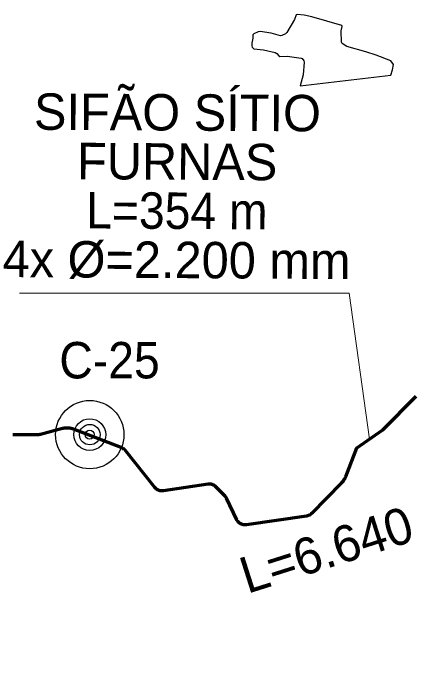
# Model space of a CAD drawing. Extents: x -1643653 to 4543381, y 1624270 to 13878484.
# Drawn here: x 717468 to 721845, y 8953455 to 8960656 of the extents above; entities that cross this region are included whole.
import ezdxf
from ezdxf.enums import TextEntityAlignment as Align

# ---------------------------------------------------------------- set-up
doc = ezdxf.new("R2010")
doc.units = 0
doc.header["$LTSCALE"] = 160
doc.linetypes.add('LONG_DASHED', pattern=[7.5, 6, -1.5])
for name, color, linetype, lineweight in [('15', 7, 'Continuous', 25), ('21', 7, 'Continuous', 25), ('50', 7, 'Continuous', 13), ('60', 7, 'Continuous', 13), ('61', 7, 'Continuous', 70)]:
    doc.layers.add(name, color=color, linetype=linetype, lineweight=lineweight)

msp = doc.modelspace()

# ---------------------------------------------------------------- linework, layer by layer
at = {"layer": '15'}
for radius in [375, 175, 112.5, 50]:
    msp.add_circle((718309, 8956027.8), radius, dxfattribs=at)
at = {"layer": '21'}
for points in [[(721081.2, 8960508.1), (721077.4, 8960519.1), (720747.7, 8960615.2), (720662.9, 8960634.1), (720587.2, 8960643), (720575.8, 8960636.9), (720556, 8960586.9), (720470.6, 8960443.6), (720458.9, 8960430), (720418.1, 8960410.7), (720402.2, 8960408.3), (720301.9, 8960437.2), (720181, 8960453.2), (720156.1, 8960451.2), (720109.1, 8960428.1), (720098.9, 8960418.5), (720097.9, 8960382.4), (720087.7, 8960324.8), (720086.7, 8960296.8), (720091.3, 8960280.8), (720111.5, 8960263.6), (720216.2, 8960251.9), (720344.2, 8960222.5), (720362.4, 8960214), (720382.8, 8960188), (720394.4, 8960180.7), (720474.7, 8960182.3), (720628.9, 8960163.3), (720641.9, 8960157.8), (720658.4, 8960133.9), (720662.8, 8960119.5), (720650.8, 8959977.9), (720618.4, 8959856.9), (721612.4, 8959974.7)], [(721612.4, 8959974.7), (721632.5, 8960032.7), (721644.1, 8960093.2), (721614, 8960131.4), (721452.9, 8960193.9), (721340.2, 8960231.7), (721132.5, 8960290.7), (721078, 8960323.4), (721072, 8960337.7), (721069.2, 8960462.3), (721081.2, 8960508.1)]]:
    msp.add_lwpolyline(points, dxfattribs=at)
at = {"layer": '50'}
msp.add_lwpolyline([(721381.2, 8955978.9), (721156.9, 8957582.7), (717536.9, 8957582.7)], dxfattribs=at)
at = {"layer": '60', "lineweight": 25}
msp.add_spline([(814781, 9009175.5), (814787.2, 9009173.4), (814796.9, 9009173.4), (814799.4, 9009172.4), (814805.1, 9009174.5), (814805.6, 9009176.5), (814811.7, 9009179.5), (814811.7, 9009179.5), (814801.5, 9009181), (814790.7, 9009181.5), (814784.1, 9009183.1), (814777.4, 9009185.1), (814778.4, 9009175.5)], degree=3, dxfattribs=at)
at = {"layer": '61', "linetype": 'LONG_DASHED'}
msp.add_line((721235.5, 8955878.6), (721527, 8956079.3), dxfattribs=at)
at = {"layer": '61'}
for points in [[(721527, 8956079.3), (721893.7, 8956451.7)], [(718108.6, 8956094.1), (718104.7, 8956095.1), (718100.8, 8956095.9), (718096.9, 8956096.7), (718092.9, 8956097.4), (718089, 8956098), (718085, 8956098.6), (718081, 8956099), (718077.1, 8956099.4), (718073.1, 8956099.7), (718069.1, 8956100), (718065.1, 8956100.1), (718061.1, 8956100.2), (718057.1, 8956100.2), (718053.1, 8956100.1), (718049.1, 8956099.9), (718045.1, 8956099.6), (718041.1, 8956099.3), (718037.1, 8956098.9), (718033.2, 8956098.4), (718029.2, 8956097.8), (718025.3, 8956097.2), (718021.3, 8956096.4), (718017.4, 8956095.6), (718013.5, 8956094.7), (718009.6, 8956093.8), (718008.8, 8956093.6), (717769.5, 8956030.4), (717765.7, 8956029.4), (717761.8, 8956028.5), (717757.8, 8956027.7), (717753.9, 8956027), (717750, 8956026.3), (717746, 8956025.7), (717742.1, 8956025.2), (717738.1, 8956024.8), (717734.1, 8956024.4), (717730.1, 8956024.1), (717726.1, 8956023.9), (717722.1, 8956023.8), (717718.1, 8956023.8), (717717.5, 8956023.8), (717484.9, 8956024.9), (717480.9, 8956025), (717476.9, 8956025.1), (717473, 8956025.3), (717469, 8956025.6), (717465, 8956026)], [(719791.3, 8955356.8), (719692.9, 8955455.4), (719690.8, 8955457.3), (719688.8, 8955459.2), (719686.6, 8955461.1), (719684.4, 8955462.9), (719682.2, 8955464.6), (719679.9, 8955466.3), (719677.6, 8955467.9), (719675.2, 8955469.4), (719672.8, 8955470.9), (719670.3, 8955472.3), (719667.8, 8955473.6), (719665.3, 8955474.9), (719662.7, 8955476.1), (719660.1, 8955477.2), (719657.5, 8955478.2), (719654.8, 8955479.2), (719652.2, 8955480.1), (719649.5, 8955480.9), (719646.7, 8955481.6), (719644, 8955482.3), (719641.2, 8955482.8), (719638.4, 8955483.3), (719635.6, 8955483.8), (719632.8, 8955484.1), (719630, 8955484.4), (719627.2, 8955484.5), (719624.3, 8955484.7), (719621.5, 8955484.7), (719618.7, 8955484.6), (719615.9, 8955484.5), (719613, 8955484.3), (719610.2, 8955484), (719607.4, 8955483.6), (719607.3, 8955483.6), (719117.6, 8955410.2), (719114.8, 8955409.8), (719112, 8955409.6), (719109.2, 8955409.3), (719106.4, 8955409.2), (719103.5, 8955409.1), (719100.7, 8955409.2), (719097.9, 8955409.2), (719095.1, 8955409.4), (719092.2, 8955409.7), (719089.4, 8955410), (719086.6, 8955410.5), (719083.8, 8955410.9), (719081.1, 8955411.5), (719078.3, 8955412.2), (719075.6, 8955412.9), (719072.9, 8955413.7), (719070.2, 8955414.6), (719067.5, 8955415.6), (719064.9, 8955416.6), (719062.3, 8955417.7), (719059.7, 8955418.9), (719057.2, 8955420.1), (719054.7, 8955421.5), (719052.2, 8955422.9), (719049.8, 8955424.3), (719047.5, 8955425.8), (719045.1, 8955427.5), (719042.8, 8955429.1), (719040.6, 8955430.8), (719038.4, 8955432.6), (719036.3, 8955434.5), (719034.2, 8955436.4), (719032.2, 8955438.4), (719030.2, 8955440.4), (719028.3, 8955442.5), (719026.4, 8955444.6), (719024.8, 8955446.5), (718696.3, 8955855.6), (718694.5, 8955857.8), (718692.7, 8955860), (718690.8, 8955862), (718688.8, 8955864), (718686.7, 8955866), (718684.7, 8955867.9), (718682.5, 8955869.8), (718680.3, 8955871.5), (718678.1, 8955873.3), (718675.8, 8955874.9), (718673.4, 8955876.5), (718671.1, 8955878), (718668.6, 8955879.5), (718666.2, 8955880.9), (718663.7, 8955882.2), (718661.1, 8955883.4), (718658.6, 8955884.6), (718655.9, 8955885.7), (718654.2, 8955886.4), (718131.5, 8956086.9), (718127.7, 8956088.3), (718123.9, 8956089.6), (718120.1, 8956090.9), (718116.3, 8956092), (718112.5, 8956093.1), (718108.6, 8956094.1)], [(721235.5, 8955878.6), (721115.9, 8955565.7), (721114.4, 8955562), (721112.9, 8955558.3), (721111.2, 8955554.7), (721109.6, 8955551)], [(721109.6, 8955551), (721107.8, 8955547.5), (721106, 8955543.9), (721104.1, 8955540.4), (721102.1, 8955536.9), (721100.1, 8955533.5), (721098, 8955530.1), (721095.8, 8955526.7), (721093.5, 8955523.4), (721091.2, 8955520.1), (721088.9, 8955516.9), (721086.4, 8955513.7), (721083.9, 8955510.6), (721081.4, 8955507.5), (721078.7, 8955504.5), (721076.1, 8955501.5), (721073.3, 8955498.6), (721071.9, 8955497.2), (720743.6, 8955162.2), (720741.6, 8955160.2), (720739.5, 8955158.3), (720737.4, 8955156.4), (720735.2, 8955154.6), (720733, 8955152.8), (720730.8, 8955151.2), (720728.4, 8955149.5), (720726.1, 8955148), (720723.7, 8955146.5), (720721.2, 8955145.1), (720718.7, 8955143.7), (720716.2, 8955142.4), (720713.7, 8955141.2), (720711.1, 8955140.1), (720708.5, 8955139), (720705.8, 8955138), (720703.1, 8955137.1), (720700.4, 8955136.3), (720697.7, 8955135.5), (720695, 8955134.8), (720692.2, 8955134.2), (720689.4, 8955133.7), (720686.6, 8955133.3), (720028.5, 8955037.2), (720025.7, 8955036.8), (720022.9, 8955036.5), (720020.1, 8955036.3), (720017.3, 8955036.2), (720014.4, 8955036.2), (720011.6, 8955036.2), (720008.8, 8955036.3), (720006, 8955036.5), (720003.1, 8955036.8), (720000.3, 8955037.1), (719997.5, 8955037.5), (719994.8, 8955038), (719992, 8955038.6), (719989.2, 8955039.3), (719986.5, 8955040), (719983.8, 8955040.8), (719981.1, 8955041.7), (719978.5, 8955042.7), (719975.8, 8955043.8), (719973.2, 8955044.9), (719970.7, 8955046.1), (719968.1, 8955047.3), (719965.7, 8955048.7), (719963.2, 8955050.1), (719960.8, 8955051.5), (719958.4, 8955053.1), (719956.1, 8955054.7), (719953.8, 8955056.4), (719951.6, 8955058.1), (719949.4, 8955059.9), (719947.2, 8955061.8), (719945.2, 8955063.7), (719943.2, 8955065.7), (719941.2, 8955067.7), (719939.3, 8955069.8), (719937.4, 8955071.9), (719935.7, 8955074.1), (719933.9, 8955076.4), (719932.3, 8955078.7), (719930.7, 8955081), (719929.2, 8955083.4), (719927.7, 8955085.8), (719926.3, 8955088.2), (719925, 8955090.8), (719923.9, 8955093), (719810.6, 8955329.7), (719809.4, 8955332.2), (719808, 8955334.7), (719806.6, 8955337.2), (719805.1, 8955339.6), (719803.6, 8955341.9), (719802, 8955344.3), (719800.3, 8955346.5), (719798.6, 8955348.8), (719796.8, 8955350.9), (719794.9, 8955353.1), (719793, 8955355.2), (719791.3, 8955356.8)]]:
    msp.add_lwpolyline(points, dxfattribs=at)

# ---------------------------------------------------------------- texts
at = {"layer": '15', "width": 0.95}
msp.add_text('C-25', height=400, dxfattribs=at).set_placement((717975.3, 8956645.1))
at = {"layer": '50'}
for s, p in [('SIFÃO SÍTIO', (719270.5, 8959366.6)), ('FURNAS', (719267.3, 8958826.6)), ('4x Ø=2.200 mm', (719260.8, 8957746.6))]:
    msp.add_text(s, height=400, rotation=359.655, dxfattribs=at).set_placement(p, align=Align.CENTER)
at = {"layer": '50', "width": 0.95}
msp.add_text('L=354 m', height=400, rotation=359.655, dxfattribs=at).set_placement((719264, 8958286.6), align=Align.CENTER)
at = {"layer": '50'}
msp.add_text('L=6.640 m', height=400, rotation=17.646, dxfattribs=at).set_placement((720038.1, 8954277.8))

doc.saveas('drawing.dxf')
